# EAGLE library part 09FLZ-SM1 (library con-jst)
CONNECTOR
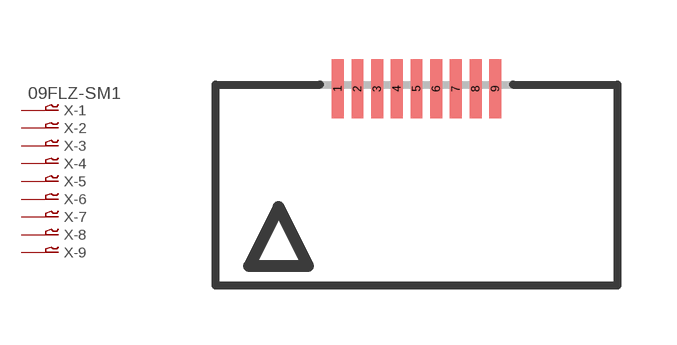
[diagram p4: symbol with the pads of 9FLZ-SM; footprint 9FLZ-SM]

Designator prefix X; gates -1=P-VN -2=P-N -3=P-N -4=P-N -5=P-N -6=P-N -7=P-N -8=P-N -9=P-N

## 09FLZ-SM1 (OC_FARNELL: unknown; OC_NEWARK: unknown)  [9FLZ-SM]
1  -1:1  pas
2  -2:1  pas
3  -3:1  pas
4  -4:1  pas
5  -5:1  pas
6  -6:1  pas
7  -7:1  pas
8  -8:1  pas
9  -9:1  pas

## Footprint 9FLZ-SM (pad centres in mm)
CONNECTOR
smd 0.3 x 1.5: 1 -2,2.5; 2 -1.5,2.5; 3 -1,2.5; 4 -0.5,2.5; 5 0,2.5; 6 0.5,2.5; 7 1,2.5; 8 1.5,2.5; 9 2,2.5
